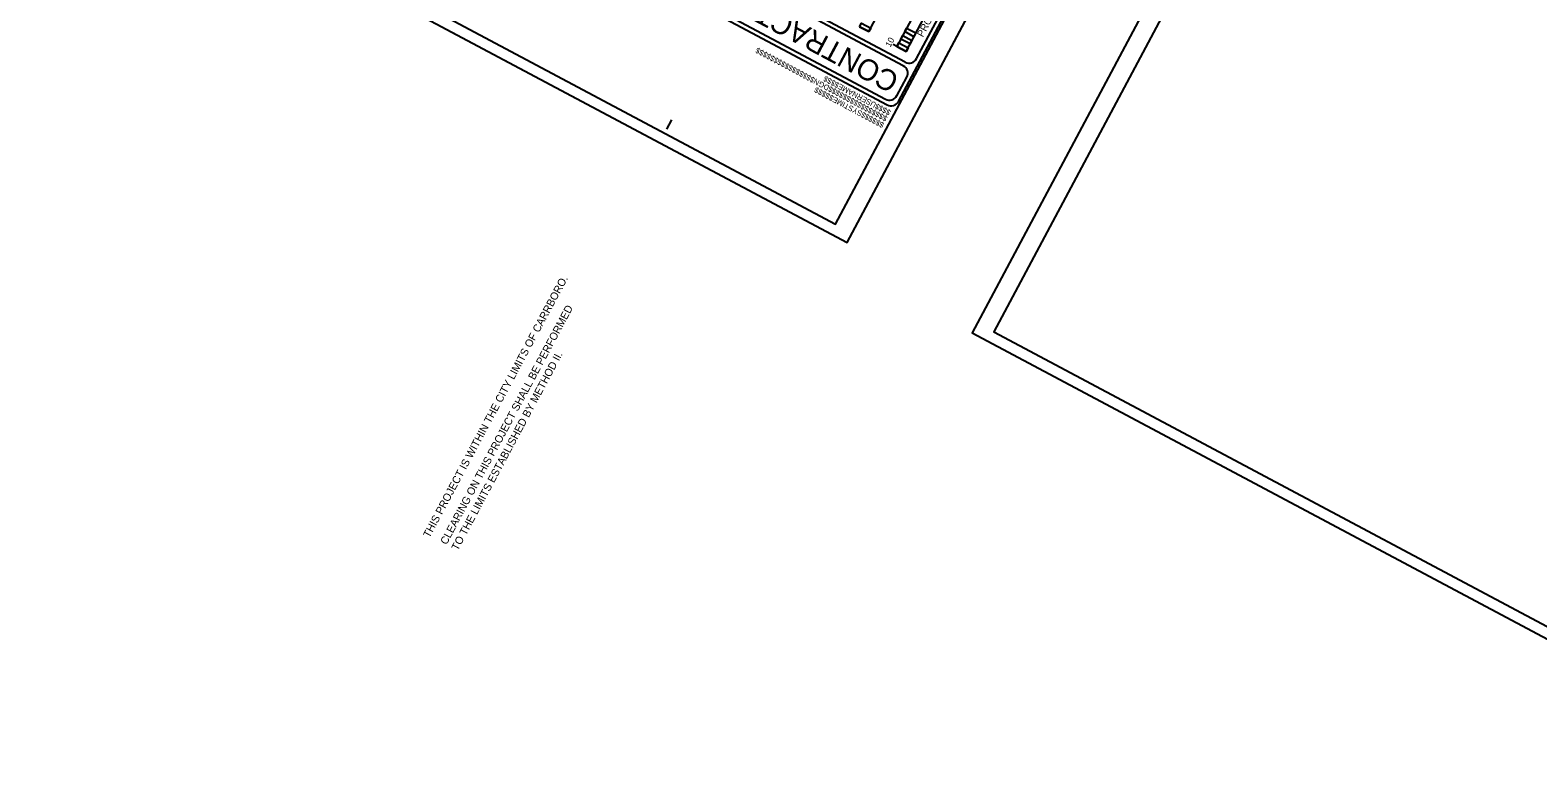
# Model space of a CAD drawing. Extents: x 1970823 to 1988115, y 770601 to 786368.
# Drawn here: x 1970823 to 1981572, y 770601 to 775863 of the extents above; entities that cross this region are included whole.
import ezdxf

# ---------------------------------------------------------------- set-up
doc = ezdxf.new("R2010")
doc.units = 0
for name, color, linetype in [('Old_Level_1', 7, 'Continuous'), ('Old_Level_50', 7, 'Continuous'), ('Old_Level_51', 7, 'Continuous'), ('Sheet Cutting Line CELL', 7, 'Continuous'), ('Sheet Data Field CELL', 7, 'Continuous'), ('Sheet Plot Border Inside CELL', 7, 'Continuous'), ('Sheet Plot Border Outside CELL', 7, 'Continuous'), ('Sheet Title CELL', 7, 'Continuous')]:
    doc.layers.add(name, color=color, linetype=linetype)

msp = doc.modelspace()

# ---------------------------------------------------------------- linework, layer by layer
at = {"layer": 'Old_Level_50'}
for points in [[(1975681, 786281), (1970979, 777456), (1976565, 774479), (1981268, 783303)], [(1982396, 782534), (1977694, 773710), (1983281, 770733), (1987983, 779557)]]:
    msp.add_lwpolyline(points, close=True, dxfattribs=at)
at = {"layer": 'Old_Level_51'}
for points in [[(1975575, 786368), (1970823, 777451), (1976648, 774347), (1981399, 783264)], [(1982290, 782621), (1977538, 773704), (1983363, 770601), (1988115, 779517)]]:
    msp.add_lwpolyline(points, close=True, dxfattribs=at)
at = {"layer": 'Sheet Cutting Line CELL'}
for p, q in [((1976648, 774347), (1981399, 783264)), ((1970823, 777451), (1976648, 774347))]:
    msp.add_line(p, q, dxfattribs=at)
at = {"layer": 'Sheet Data Field CELL'}
msp.add_line((1976986, 775302), (1976986, 775302), dxfattribs=at)
at = {"layer": 'Sheet Plot Border Inside CELL'}
msp.add_lwpolyline([(1976565, 774479), (1981268, 783303), (1975681, 786281), (1970979, 777456)], close=True, dxfattribs=at)
at = {"layer": 'Sheet Plot Border Outside CELL'}
msp.add_lwpolyline([(1975575, 786368), (1970823, 777451), (1976648, 774347), (1981399, 783264)], close=True, dxfattribs=at)
at = {"layer": 'Sheet Title CELL'}
for p, q in [((1977048, 775609), (1971647, 778487)), ((1976803, 775852), (1977226, 776646)), ((1977425, 776540), (1977002, 775746)), ((1977425, 776540), (1977002, 775746)), ((1977425, 776540), (1977002, 775746)), ((1977068, 775711), (1977491, 776505)), ((1977062, 775635), (1976215, 776087)), ((1976737, 775887), (1976803, 775852)), ((1977002, 775746), (1976975, 775760)), ((1977002, 775746), (1976975, 775760)), ((1977002, 775746), (1976975, 775760)), ((1976975, 775760), (1976975, 775760)), ((1977002, 775746), (1977068, 775711)), ((1977002, 775746), (1977002, 775746)), ((1977002, 775746), (1977002, 775746)), ((1977002, 775746), (1977002, 775746)), ((1976986, 775302), (1976986, 775302)), ((1976986, 775302), (1976986, 775302)), ((1976986, 775302), (1976986, 775302)), ((1976986, 775302), (1976986, 775302)), ((1975363, 775157), (1975398, 775224)), ((1975363, 775157), (1975398, 775224))]:
    msp.add_line(p, q, dxfattribs=at)
for points in [[(1977015, 775355), (1981191, 783191)], [(1971520, 778249), (1976921, 775371)], [(1971480, 778236), (1976933, 775330)], [(1971480, 778236), (1976933, 775330)], [(1977143, 775660), (1977581, 776481)], [(1977002, 775395), (1977073, 775528)]]:
    msp.add_lwpolyline(points, dxfattribs=at)
for points in [[(1976737, 775887), (1976751, 775913), (1976817, 775878), (1976803, 775852)], [(1977030, 775799), (1977044, 775825), (1977110, 775790), (1977096, 775764)], [(1977058, 775852), (1977072, 775878), (1977138, 775843), (1977124, 775816)], [(1977002, 775746), (1977016, 775772), (1977082, 775737), (1977068, 775711)]]:
    msp.add_lwpolyline(points, close=True, dxfattribs=at)
for centre, start, end in [((1977020, 775556), 331.9471, 61.9471), ((1977090, 775688), 241.9471, 331.9471), ((1976949, 775424), 241.9471, 331.9471), ((1976961, 775383), 241.9471, 331.9471)]:
    msp.add_arc(centre, 60, start, end, dxfattribs=at)

# ---------------------------------------------------------------- texts
at = {"layer": 'Old_Level_1'}
for s, p in [('THIS PROJECT IS WITHIN THE CITY LIMITS OF CARRBORO.', (1973670, 772237)), ('CLEARING ON THIS PROJECT SHALL BE PERFORMED', (1973792, 772188)), ('TO THE LIMITS ESTABLISHED BY METHOD II.', (1973872, 772146))]:
    msp.add_text(s, height=55, rotation=61.9471, dxfattribs=at).set_placement(p)
at = {"layer": 'Sheet Data Field CELL'}
msp.add_text('10', height=45, rotation=61.9471, dxfattribs=at).set_placement((1976956, 775737))
at = {"layer": 'Sheet Title CELL'}
for s, height, rotation, p in [('CONTRACT: C203028', 150, 151.9471, (1977029, 775541)), ('PROFILE (VERTICAL)', 51, 61.9471, (1977188, 775809)), ('$$$$$$$$$$$$$$$$DGN$$$$$$$$$$$$$$$$', 39.38, 151.9471, (1976939, 775244)), ('$$$$$$SYSTIME$$$$$', 39.38, 151.9471, (1976916, 775198)), ('$$$$USERNAME$$$$', 39.38, 151.9471, (1976963, 775287))]:
    msp.add_text(s, height=height, rotation=rotation, dxfattribs=at).set_placement(p)

doc.saveas('drawing.dxf')
